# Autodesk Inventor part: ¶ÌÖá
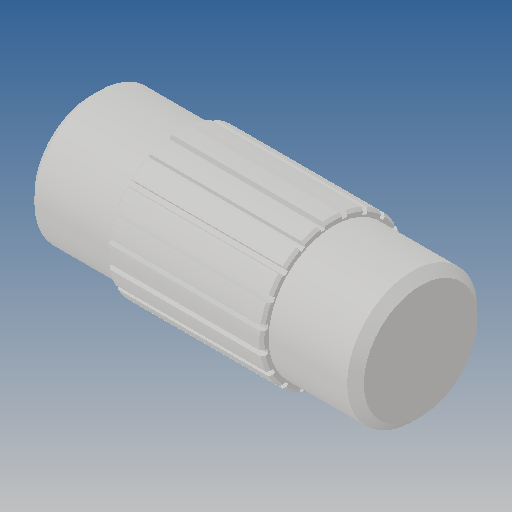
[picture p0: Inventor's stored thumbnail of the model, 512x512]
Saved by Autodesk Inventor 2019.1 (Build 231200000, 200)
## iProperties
Created: 2012-10
Part Number: ¶ÌÖá
Material: Ogólny
Document SubType Name: Modeling
Designer: CADENGINEERING4
Density: 1 g/cm^3
Appearance: Domyślna
Author: CADENGINEERING4
Revision Number: ÈÎºÎ
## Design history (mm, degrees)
feature "À­Éì5"
node "Bryła1"
